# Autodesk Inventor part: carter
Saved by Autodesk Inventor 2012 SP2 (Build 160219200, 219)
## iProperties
Created: 2013-04
Part Number: carter
Material: Default
Document SubType Name: Modeling
Designer: papa
Density: 1 g/cm^3
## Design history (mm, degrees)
node "carter1"
node "carter"
node "Base1"
